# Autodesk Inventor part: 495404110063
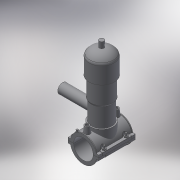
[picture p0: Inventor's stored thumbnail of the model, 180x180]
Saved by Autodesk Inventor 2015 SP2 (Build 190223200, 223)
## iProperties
Created: 2017-07
Part Number: 495404110063
Material: Generic
Description: PLASSON TAPPING VALVE 110-63
Document SubType Name: Modeling
Designer: KIM
Density: 1 g/cm^3
Appearance: Default
Author: KIM
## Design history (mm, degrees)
derived "495404-4954S4.ipt"
feature "Solid1::495404-4954S4.ipt"
feature "Solid2::495404-4954S4.ipt"
tag "TaggingFeature1"
body "Solid1"
body "Solid2"
other parameters: "d2" = 148, "d3" = 27.5, "d4" = 118, "d5" = 0, "d6" = 0.1, "d8" = 0, "d19" = 6, "d20" = 6, "d21" = 70.8, "d23" = 0, "d24" = 35.4, "d26" = 0, "d27" = 3, "d28" = 3, "d29" = 3, "d30" = 36.66667, "d31" = 6, "d32" = 0, "d33" = 0, "d34" = 0.6, "d40" = 71.5, "d47" = 119.75, "d70" = 15, "d72" = 0, "d73" = 6, "d75" = 5, "d76" = 0, "d77" = 5.5, "d78" = 85, "d79" = 15, "d80" = 47.2, "d82" = 5 deg, "d84" = 4, "d85" = 14, "d86" = 0, "d87" = 3, "d88" = 0, "d89" = 1, "d90" = 1, "d91" = 94.4, "d92" = 0, "d93" = 0.5, "d94" = 57.89474, "d96" = 141.625, "d97" = 2.36, "d98" = 0, "d120" = 140 deg, "d121" = 24.228, "d122" = 20 deg, "d123" = 275, "d124" = 82.5, "d126" = 0, "d143" = 113.3, "d145" = 21.15385, "d149" = 1.65, "d150" = 23.26923, "d153" = 118, "d154" = 0, "d156" = 68.75, "d157" = 160 deg, "d159" = 5.5, "d161" = 1.65, "d162" = 70.8, "d163" = 0, "d164" = 55, "d167" = 11, "d168" = 67.07317, "d170" = 3, "d172" = 0, "d173" = 1, "d175" = 55, "d176" = 20 deg, "d177" = 7.7, "d178" = 27.5, "d180" = 0, "d183" = 11, "d184" = 6.16, "d185" = 38.35, "d186" = 38.35, "d187" = 68.75, "d188" = 8.25, "d189" = 7.7, "d190" = 0, "d191" = 103.125, "d193" = 6.8, "d194" = 2.95, "d195" = 90 deg, "d197" = 0, "d199" = 0, "d205" = 14.64, "d206" = 81.33333, "d207" = 244, "d208" = 224.48, "d209" = 207.4, "d210" = 200.08, "d211" = 146.4, "d212" = 85.4, "d213" = 65.88, "d214" = 73.2, "d216" = 19.52, "d217" = 70.76, "d218" = 80.52, "d222" = 0, "d223" = 137.5, "d224" = 186, "d225" = 51, "d226" = 63, "d229" = 186, "d230" = 0, "B_" = 148, "H_" = 186, "L_" = 118, "d_t" = 6, "d_1" = 63, "H_1" = 51, "H_2" = 244, "d148" = 1.65, "d160" = 1.65, "d169" = 3, "d192" = 6.8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
